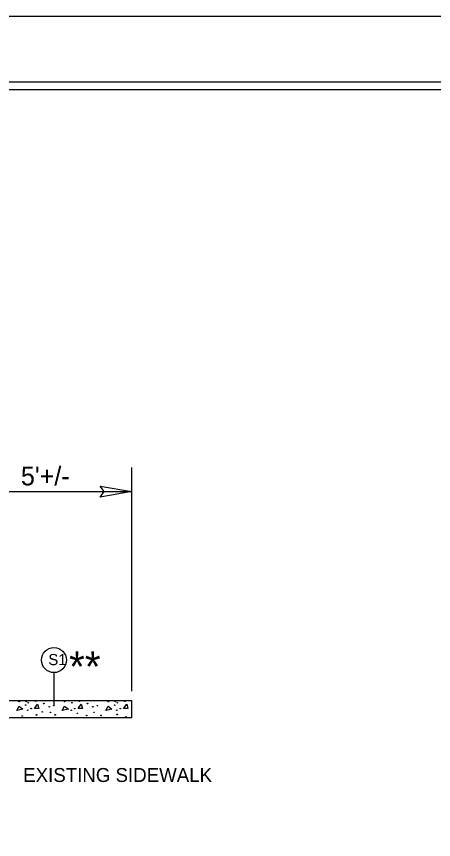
# Model space of a CAD drawing. Extents: x 1022283 to 1026986, y 174822 to 180471.
# Drawn here: x 1024377 to 1024733, y 176870 to 177572 of the extents above; entities that cross this region are included whole.
import ezdxf

# ---------------------------------------------------------------- set-up
doc = ezdxf.new("R2010")
doc.units = 0
for name, color, linetype in [('Default', 7, 'Continuous'), ('Prop Dimension', 7, 'Continuous'), ('Prop Terminator CELL', 7, 'Continuous'), ('Sheet Cutting Line CELL', 7, 'Continuous'), ('Sheet Plot Border Inside CELL', 7, 'Continuous'), ('Sheet Plot Border Outside CELL', 7, 'Continuous'), ('Sheet Typical CELL', 7, 'Continuous'), ('Typical Curb CELL', 7, 'Continuous'), ('Typical ID Circle CELL', 7, 'Continuous'), ('Typical Slope Point Local CELL', 7, 'Continuous'), ('Typical Text General CELL', 7, 'Continuous'), ('Typical Text ID Circle CELL', 7, 'Continuous')]:
    doc.layers.add(name, color=color, linetype=linetype)

msp = doc.modelspace()

# ---------------------------------------------------------------- linework, layer by layer
at = {"layer": 'Default'}
for p, q in [((1024475.62, 176996.93), (1024475.62, 177187.75)), ((1024338.25, 177167.18), (1024475.62, 177167.18))]:
    msp.add_line(p, q, dxfattribs=at)
at = {"layer": 'Prop Terminator CELL'}
msp.add_lwpolyline([(1024448.62, 177171.83), (1024475.62, 177167.18), (1024448.47, 177162.38), (1024451.92, 177167.18)], close=True, dxfattribs=at)
at = {"layer": 'Sheet Cutting Line CELL'}
msp.add_line((1026493.22, 177572.45), (1022283.22, 177572.45), dxfattribs=at)
at = {"layer": 'Sheet Plot Border Inside CELL'}
msp.add_lwpolyline([(1026481.97, 177516.33), (1022315.72, 177516.33), (1022315.72, 174878.58), (1026481.97, 174878.58)], close=True, dxfattribs=at)
at = {"layer": 'Sheet Plot Border Outside CELL'}
msp.add_lwpolyline([(1026493.22, 177572.45), (1022283.22, 177572.45), (1022283.22, 174822.45), (1026493.22, 174822.45)], close=True, dxfattribs=at)
at = {"layer": 'Sheet Typical CELL'}
msp.add_lwpolyline([(1026450.72, 177509.95), (1022700.72, 177509.95), (1022700.72, 174884.95), (1026450.72, 174884.95)], close=True, dxfattribs=at)
at = {"layer": 'Typical Curb CELL'}
for p, q in [((1024475.62, 176988.66), (1024338.25, 176988.66)), ((1024475.62, 176988.66), (1024338.25, 176988.66)), ((1024392.58, 176982.03), (1024395.23, 176985.74)), ((1024392.58, 176982.03), (1024395.23, 176985.74)), ((1024395.23, 176985.74), (1024396.3, 176982.22)), ((1024395.23, 176985.74), (1024396.3, 176982.22)), ((1024429.71, 176982.03), (1024432.4, 176985.74)), ((1024429.71, 176982.03), (1024432.4, 176985.74)), ((1024432.4, 176985.74), (1024433.46, 176982.22)), ((1024432.4, 176985.74), (1024433.46, 176982.22)), ((1024468.47, 176982.03), (1024471.12, 176985.74)), ((1024468.47, 176982.03), (1024471.12, 176985.74)), ((1024471.12, 176985.74), (1024472.19, 176982.22)), ((1024471.12, 176985.74), (1024472.19, 176982.22)), ((1024475.62, 176974.13), (1024475.62, 176988.66)), ((1024475.62, 176974.13), (1024475.62, 176988.66)), ((1024377.56, 176980.45), (1024379.5, 176984)), ((1024377.56, 176980.45), (1024379.5, 176984)), ((1024382.7, 176981.67), (1024377.56, 176980.45)), ((1024382.7, 176981.67), (1024377.56, 176980.45)), ((1024379.5, 176984), (1024382.7, 176981.67)), ((1024379.5, 176984), (1024382.7, 176981.67)), ((1024396.3, 176982.22), (1024392.58, 176982.03)), ((1024396.3, 176982.22), (1024392.58, 176982.03)), ((1024416.29, 176980.45), (1024418.23, 176984)), ((1024416.29, 176980.45), (1024418.23, 176984)), ((1024421.42, 176981.67), (1024416.29, 176980.45)), ((1024421.42, 176981.67), (1024416.29, 176980.45)), ((1024418.23, 176984), (1024421.42, 176981.67)), ((1024418.23, 176984), (1024421.42, 176981.67)), ((1024433.46, 176982.22), (1024429.71, 176982.03)), ((1024433.46, 176982.22), (1024429.71, 176982.03)), ((1024453.45, 176980.45), (1024455.39, 176984)), ((1024453.45, 176980.45), (1024455.39, 176984)), ((1024458.59, 176981.67), (1024453.45, 176980.45)), ((1024458.59, 176981.67), (1024453.45, 176980.45)), ((1024455.39, 176984), (1024458.59, 176981.67)), ((1024455.39, 176984), (1024458.59, 176981.67)), ((1024472.19, 176982.22), (1024468.47, 176982.03)), ((1024472.19, 176982.22), (1024468.47, 176982.03)), ((1024475.62, 176974.13), (1024338.25, 176974.13))]:
    msp.add_line(p, q, dxfattribs=at)
for centre in [(1024379.51, 176988.06), (1024379.51, 176988.06), (1024385, 176985.06), (1024385, 176985.06), (1024385.53, 176988.06), (1024385.53, 176988.06), (1024387.26, 176987), (1024387.26, 176987), (1024393.64, 176988.24), (1024393.64, 176988.24), (1024400.54, 176986.29), (1024400.54, 176986.29), (1024409.04, 176984.52), (1024409.04, 176984.52), (1024418.24, 176988.06), (1024418.24, 176988.06), (1024424.42, 176987), (1024424.42, 176987), (1024430.79, 176988.24), (1024430.79, 176988.24), (1024437.7, 176986.29), (1024437.7, 176986.29), (1024446.2, 176984.52), (1024446.2, 176984.52), (1024455.4, 176988.06), (1024455.4, 176988.06), (1024460.89, 176985.06), (1024460.89, 176985.06), (1024461.42, 176988.06), (1024461.42, 176988.06), (1024463.15, 176987), (1024463.15, 176987), (1024469.53, 176988.24), (1024469.53, 176988.24), (1024386.77, 176980.63), (1024386.77, 176980.63), (1024389.75, 176982.04), (1024389.75, 176982.04), (1024399.24, 176979.23), (1024399.24, 176979.23), (1024405.15, 176983.64), (1024405.15, 176983.64), (1024406.2, 176978.86), (1024406.2, 176978.86), (1024423.92, 176980.63), (1024423.92, 176980.63), (1024426.9, 176982.04), (1024426.9, 176982.04), (1024429.15, 176978), (1024429.15, 176978), (1024442.3, 176983.64), (1024442.3, 176983.64), (1024443.36, 176978.86), (1024443.36, 176978.86), (1024462.66, 176980.63), (1024462.66, 176980.63), (1024465.64, 176982.04), (1024465.64, 176982.04), (1024382.06, 176975.74), (1024382.06, 176975.74), (1024394.27, 176976.71), (1024394.27, 176976.71), (1024410.22, 176976.71), (1024410.22, 176976.71), (1024437.03, 176976.13), (1024437.03, 176976.13), (1024449.3, 176976.13), (1024449.3, 176976.13), (1024463, 176977.1), (1024463, 176977.1), (1024470.43, 176975.16), (1024470.43, 176975.16)]:
    msp.add_circle(centre, 0.249, dxfattribs=at)
at = {"layer": 'Typical ID Circle CELL'}
msp.add_line((1024409.15, 177012.76), (1024409.15, 176985.23), dxfattribs=at)
msp.add_circle((1024409.15, 177023.41), 10.65, dxfattribs=at)

# ---------------------------------------------------------------- texts
at = {"layer": 'Prop Dimension'}
msp.add_text("5'+/-", height=16, dxfattribs=at).set_placement((1024381, 177172.45))
at = {"layer": 'Typical Slope Point Local CELL'}
msp.add_text('**', height=25.771, dxfattribs=at).set_placement((1024422.03, 177005.02))
at = {"layer": 'Typical Text General CELL'}
msp.add_text('EXISTING SIDEWALK', height=11.8979, dxfattribs=at).set_placement((1024382.95, 176919.45))
at = {"layer": 'Typical Text ID Circle CELL'}
msp.add_text('S1', height=9.534, dxfattribs=at).set_placement((1024404.35, 177019.1))

doc.saveas('drawing.dxf')
